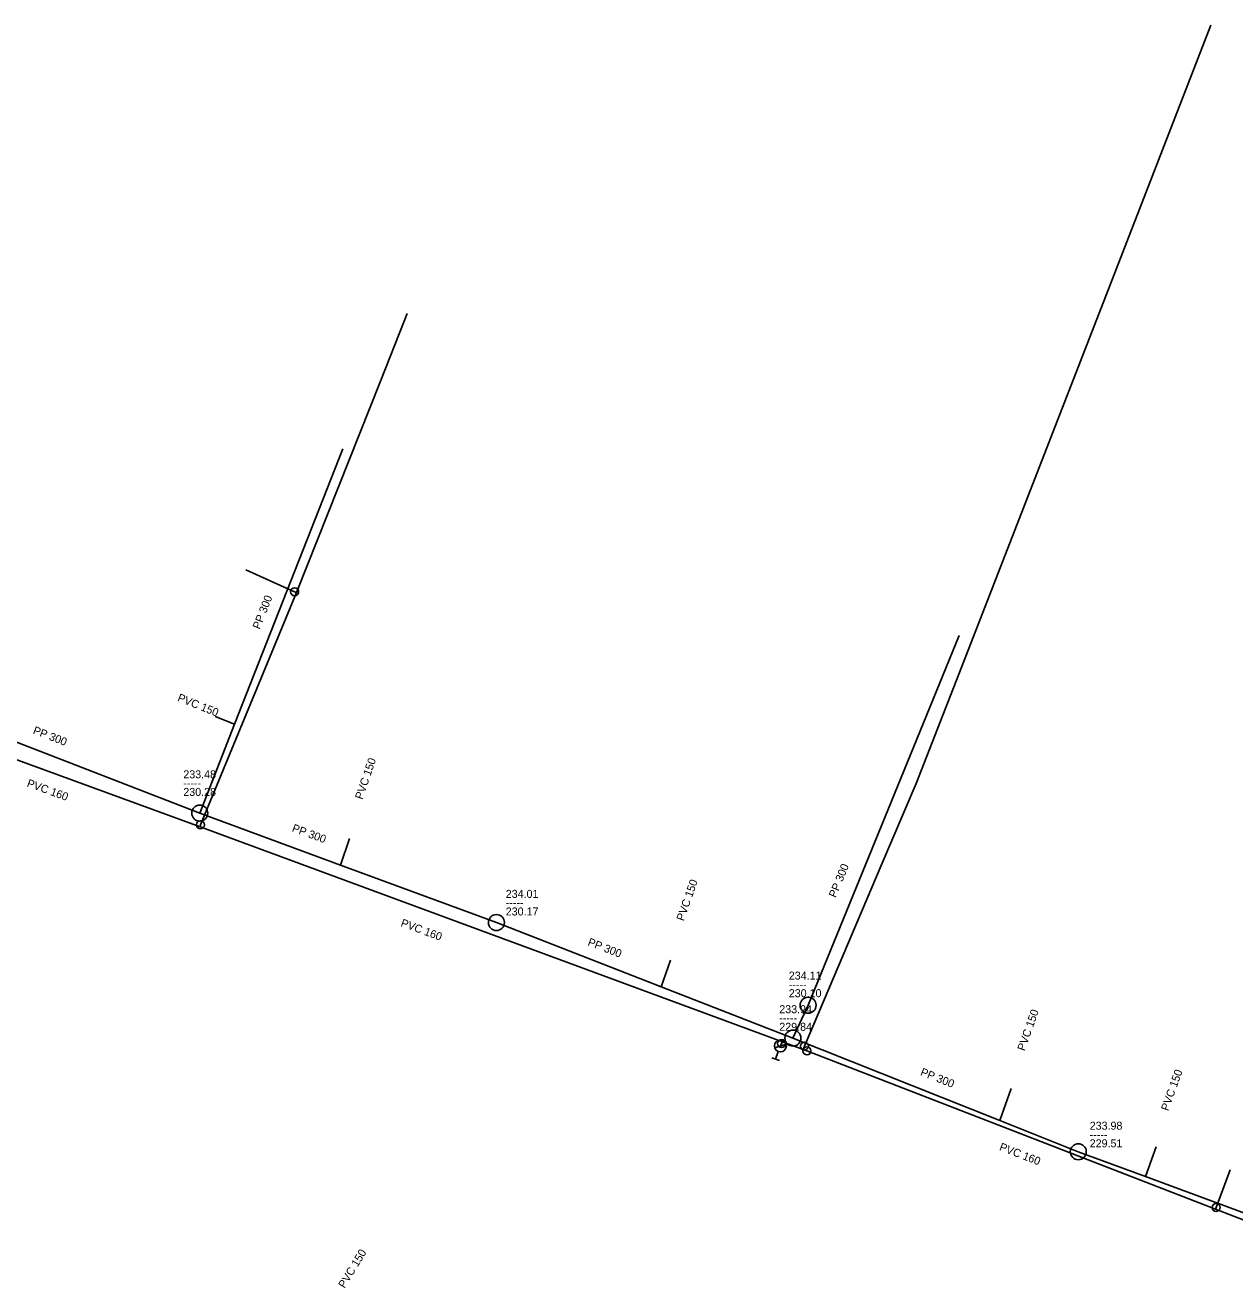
# Model space of a CAD drawing. Extents: x -771542 to -770341, y -1050442 to -1049881.
# Drawn here: x -771091.6 to -770940.3, y -1050160.7 to -1050004.3 of the extents above; entities that cross this region are included whole.
import ezdxf

# ---------------------------------------------------------------- set-up
doc = ezdxf.new("R2010")
doc.units = 0
doc.layers.add('Level 0', color=7, linetype='Continuous')

msp = doc.modelspace()

# ---------------------------------------------------------------- linework, layer by layer
at = {"layer": 'Level 0'}
for p, q in [((-770943.34, -1050004.29), (-770955.89, -1050036.76)), ((-770955.89, -1050036.76), (-770974.18, -1050083.68)), ((-771044.18, -1050041.31), (-771043.79, -1050040.33)), ((-771047.15, -1050048.81), (-771044.18, -1050041.31)), ((-771057.63, -1050075.21), (-771047.15, -1050048.81)), ((-771051.85, -1050057.23), (-771055.3, -1050066.04)), ((-771055.3, -1050066.04), (-771065.38, -1050091.66)), ((-771057.87, -1050075.1), (-771063.98, -1050072.37)), ((-771069.66, -1050104.23), (-771057.63, -1050075.21)), ((-771057.63, -1050075.21), (-771057.87, -1050075.1)), ((-770974.79, -1050080.58), (-770978.87, -1050090.58)), ((-770974.18, -1050083.68), (-770980.16, -1050099.05)), ((-771065.38, -1050091.66), (-771069.74, -1050102.77)), ((-771065.38, -1050091.66), (-771067.8, -1050090.68)), ((-770978.87, -1050090.58), (-770993.67, -1050126.78)), ((-771101.83, -1050092.77), (-771069.68, -1050104.49)), ((-771096.66, -1050092.37), (-771069.74, -1050102.77)), ((-770980.16, -1050099.05), (-770984.54, -1050109.33)), ((-771069.74, -1050102.77), (-771052.14, -1050109.26)), ((-771069.68, -1050104.49), (-771069.66, -1050104.23)), ((-771069.68, -1050104.49), (-770996.89, -1050131.35)), ((-771052.14, -1050109.26), (-771051, -1050105.95)), ((-771052.14, -1050109.26), (-771032.65, -1050116.45)), ((-770984.54, -1050109.33), (-770994.14, -1050131.89)), ((-771032.65, -1050116.45), (-771012.04, -1050124.47)), ((-771012.04, -1050124.47), (-771010.87, -1050121.14)), ((-771012.04, -1050124.47), (-770995.57, -1050130.88)), ((-770993.67, -1050126.78), (-770995.57, -1050130.88)), ((-770995.57, -1050130.88), (-770969.69, -1050141.18)), ((-770996.43, -1050131.63), (-770997.85, -1050132.09)), ((-770997.4, -1050132.56), (-770997.74, -1050133.5)), ((-770997, -1050131.57), (-770997.14, -1050131.86)), ((-770996.89, -1050131.35), (-770997, -1050131.57)), ((-770996.89, -1050131.35), (-770994.29, -1050132.31)), ((-770994.14, -1050131.89), (-770994.29, -1050132.31)), ((-770994.29, -1050132.31), (-770993.82, -1050132.48)), ((-770993.82, -1050132.48), (-770942.74, -1050152.26)), ((-770997.27, -1050133.68), (-770998.21, -1050133.33)), ((-770969.69, -1050141.18), (-770968.27, -1050137.18)), ((-770969.69, -1050141.18), (-770959.89, -1050145.08)), ((-770959.89, -1050145.08), (-770951.49, -1050148.19)), ((-770951.49, -1050148.19), (-770950.16, -1050144.48)), ((-770951.49, -1050148.19), (-770918.61, -1050160.36)), ((-770942.66, -1050152.05), (-770940.91, -1050147.36)), ((-770942.74, -1050152.26), (-770942.66, -1050152.05)), ((-770942.74, -1050152.26), (-770939.29, -1050153.6))]:
    msp.add_line(p, q, dxfattribs=at)
for centre, radius in [((-771057.87, -1050075.1), 0.5), ((-771069.74, -1050102.77), 1), ((-771069.66, -1050104.23), 0.5), ((-771032.65, -1050116.45), 1), ((-770993.67, -1050126.78), 1), ((-770997.14, -1050131.86), 0.75), ((-770997, -1050131.57), 0.5), ((-770995.57, -1050130.88), 1), ((-770994.14, -1050131.89), 0.5), ((-770993.82, -1050132.48), 0.5), ((-770959.89, -1050145.08), 1), ((-770942.66, -1050152.05), 0.5)]:
    msp.add_circle(centre, radius, dxfattribs=at)

# ---------------------------------------------------------------- texts
for s, rotation, p in [('PP 300', 68.523, (-771062.24, -1050079.87)), ('PVC 150', 337.954, (-771072.6, -1050088.72)), ('PP 300', 338.877, (-771090.67, -1050092.81)), ('PVC 150', 70.996, (-771049.41, -1050101.14)), ('PVC 160', 339.971, (-771091.43, -1050099.42)), ('PP 300', 339.759, (-771058.28, -1050105.03)), ('PP 300', 67.763, (-770990.21, -1050113.41)), ('PVC 150', 70.641, (-771009.23, -1050116.32)), ('PVC 160', 339.734, (-771044.69, -1050116.88)), ('PP 300', 338.737, (-771021.31, -1050119.26)), ('PVC 150', 70.455, (-770966.61, -1050132.56)), ('PP 300', 338.298, (-770979.72, -1050135.5)), ('PVC 150', 70.278, (-770948.65, -1050140.06)), ('PVC 160', 338.774, (-770969.85, -1050144.86)), ('PVC 150', 58.635, (-771051.63, -1050162.22))]:
    msp.add_text(s, height=1, rotation=rotation, dxfattribs=at).set_placement(p)
for s, p in [('233.48', (-771071.79, -1050098.42)), ('-----', (-771071.79, -1050099.52)), ('230.28', (-771071.79, -1050100.62)), ('234.01', (-771031.48, -1050113.36)), ('-----', (-771031.48, -1050114.46)), ('230.17', (-771031.48, -1050115.56)), ('234.11', (-770996.09, -1050123.57)), ('-----', (-770996.09, -1050124.67)), ('230.10', (-770996.09, -1050125.77)), ('233.94', (-770997.28, -1050127.77)), ('-----', (-770997.28, -1050128.87)), ('229.84', (-770997.28, -1050129.97)), ('233.98', (-770958.47, -1050142.33)), ('-----', (-770958.47, -1050143.43)), ('229.51', (-770958.47, -1050144.53))]:
    msp.add_text(s, height=1, dxfattribs=at).set_placement(p)

doc.saveas('drawing.dxf')
